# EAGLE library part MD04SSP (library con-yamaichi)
YAMAICHI CONNECTOR
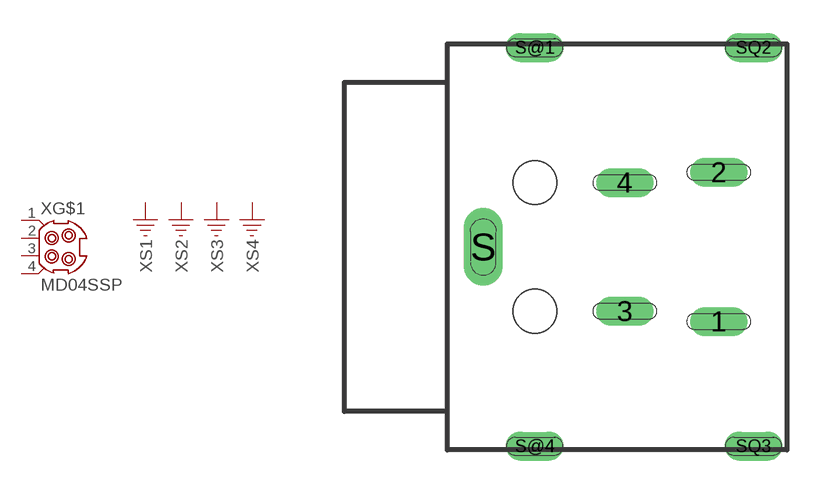
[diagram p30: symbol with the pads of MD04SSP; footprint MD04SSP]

Designator prefix X; gates G$1=MD04SSP S1=SHIELD S2=SHIELD S3=SHIELD S4=SHIELD

## MD04SSP (OC_FARNELL: unknown; OC_NEWARK: unknown)  [MD04SSP]
1  G$1:1  pas
2  G$1:2  pas
3  G$1:3  pas
4  G$1:4  pas
S@1  S1:1  pas
S@4  S2:1  pas
SQ2  S3:1  pas
SQ3  S4:1  pas

## Footprint MD04SSP (pad centres in mm)
Mini Din YAMAICHI CONNECTOR
drill 0.61 long: 1 3.65,-2.9; 2 3.65,2.9; 3 0,-2.5; 4 0,2.5; S@1 -3.5,7.75; S@4 -3.5,-7.75; SQ2 5,7.75; SQ3 5,-7.75
drill 1 long: S -5.5,0
hole 1.7 at -3.5,-2.5
hole 1.7 at -3.5,2.5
